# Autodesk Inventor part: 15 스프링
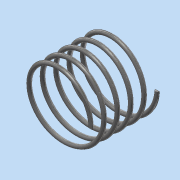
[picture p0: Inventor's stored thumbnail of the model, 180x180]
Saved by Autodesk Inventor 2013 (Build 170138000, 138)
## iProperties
Created: 2016-06
Part Number: 15 스프링
Material: 강철, 탄소
Document SubType Name: Modeling
Designer: Administrator
Density: 7.87 g/cm^3
Mass: 1.62957 g
Surface Area: 8.35994 cm^2
Volume: 0.207061 cm^3
Author: Administrator
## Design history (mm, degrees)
sketch "스케치1"
  geometry: L1 (0, 0)-(8.5, 0); L2 (8.5, 0)-(8.5, 16.67); L3 (8.5, 16.67)-(0, 16.67); L4 (0, 16.67)-(0, 0); C1 r 0.5 at (8.5, 0)
  constraints: 8 end point, 2 parallel, 1 centre point, 1 coincident, 1 horizontal, 1 perpendicular
  dimensions: "d0" = 16.66987 distance of L3.end L1.start (derived); "d1" = 1 diameter of C1; "d2" = 17 diameter of L2 L4
feature "코일1" sketch "스케치1" pitch "d3" = 10; turns "d5" = 5; dims "d4" = 16.66987 (= d0), "d6" = 0, angle "d7" = 90 deg, angle "d8" = 90 deg, "d9" = 0, "d10" = 0
sketch "스케치2"
  geometry: L1 (0, 15)-(16.67, 15); L2 (16.67, 15)-(16.67, -15); L3 (16.67, -15)-(0, -15); L4 (0, -15)-(0, 15); 4 further points
  constraints: 8 end point, 2 coincident, 2 midpoint, 2 parallel, 1 horizontal, 1 perpendicular
  dimensions: "d11" = 30 distance of L1.end L2.end
extrude "돌출1" sketch "스케치2" stored distance "d13" = 50; taper "d14" = 0 deg
node "솔리드1"
